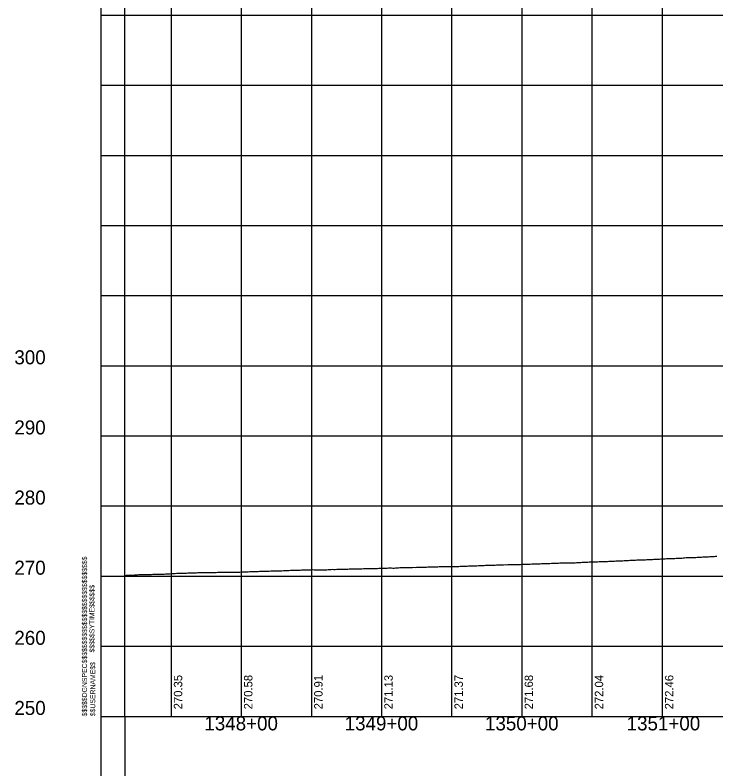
# Model space of a CAD drawing. Extents: x -90830 to 2015517, y -20856 to 836331.
# Drawn here: x 19162 to 19662, y 20025 to 20563 of the extents above; entities that cross this region are included whole.
import ezdxf

# ---------------------------------------------------------------- set-up
doc = ezdxf.new("R2010")
doc.units = 0
for name, color, linetype in [('Level 1', 7, 'Continuous'), ('RD_DDB_ElevTX', 7, 'Continuous'), ('RD_DDB_Profile_EX', 7, 'Continuous'), ('RD_DDB_StaTX', 7, 'Continuous'), ('RD_DDB_StripGrade', 7, 'Continuous'), ('RD_GPK_Profile_Cell', 7, 'Continuous'), ('RD_SHT_MatchLine', 7, 'Continuous')]:
    doc.layers.add(name, color=color, linetype=linetype)

msp = doc.modelspace()

# ---------------------------------------------------------------- linework, layer by layer
at = {"layer": 'Level 1'}
for p, q in [((19223.46, 21062.87), (19223.46, 20562.87)), ((19273.46, 21062.87), (19273.46, 20562.87)), ((19323.46, 21062.87), (19323.46, 20562.87)), ((19373.46, 21062.87), (19373.46, 20562.87)), ((19423.46, 21062.87), (19423.46, 20562.87)), ((19473.46, 21062.87), (19473.46, 20562.87)), ((19523.46, 21062.87), (19523.46, 20562.87)), ((19573.46, 21062.87), (19573.46, 20562.87)), ((19623.46, 21062.87), (19623.46, 20562.87)), ((19223.46, 20562.87), (20823.46, 20562.87)), ((19223.46, 20562.87), (20823.46, 20562.87)), ((19223.46, 20562.87), (19223.46, 20062.87)), ((19273.46, 20562.87), (19273.46, 20062.87)), ((19323.46, 20562.87), (19323.46, 20062.87)), ((19373.46, 20562.87), (19373.46, 20062.87)), ((19423.46, 20562.87), (19423.46, 20062.87)), ((19473.46, 20562.87), (19473.46, 20062.87)), ((19523.46, 20562.87), (19523.46, 20062.87)), ((19573.46, 20562.87), (19573.46, 20062.87)), ((19623.46, 20562.87), (19623.46, 20062.87)), ((19223.46, 20512.87), (20823.46, 20512.87)), ((19223.46, 20462.87), (20823.46, 20462.87)), ((19223.46, 20412.87), (20823.46, 20412.87)), ((19223.46, 20362.87), (20823.46, 20362.87)), ((19223.46, 20312.87), (20823.46, 20312.87)), ((19223.46, 20262.87), (20823.46, 20262.87)), ((19223.46, 20212.87), (20823.46, 20212.87)), ((19223.46, 20162.87), (20823.46, 20162.87)), ((19223.46, 20112.87), (20823.46, 20112.87)), ((19223.46, 20062.87), (20823.46, 20062.87))]:
    msp.add_line(p, q, dxfattribs=at)
at = {"layer": 'RD_DDB_Profile_EX'}
for points in [[(19640.51, 20176.02), (19641.51, 20176.02), (19642.51, 20176.04), (19643.51, 20176.13), (19644.51, 20176.17), (19645.51, 20176.18), (19646.51, 20176.22), (19647.51, 20176.24), (19648.51, 20176.33), (19649.51, 20176.33), (19650.51, 20176.38), (19651.51, 20176.48), (19652.51, 20176.52), (19653.51, 20176.53), (19654.51, 20176.62), (19655.51, 20176.67), (19656.51, 20176.72), (19657.51, 20176.77), (19658.51, 20176.83), (19659.51, 20176.92), (19660.51, 20176.93), (19661.51, 20176.98), (19662.51, 20177.04)], [(19440.51, 20168.96), (19441.51, 20168.96), (19442.51, 20169.01), (19443.51, 20169.1), (19444.51, 20169.06), (19445.51, 20169.11), (19446.51, 20169.16), (19447.51, 20169.12), (19448.51, 20169.16), (19449.51, 20169.21), (19450.51, 20169.26), (19451.51, 20169.27), (19452.51, 20169.27), (19453.51, 20169.31), (19454.51, 20169.32), (19455.51, 20169.27), (19456.51, 20169.4), (19457.51, 20169.41), (19458.51, 20169.46), (19459.51, 20169.51), (19460.51, 20169.55), (19461.51, 20169.56), (19462.51, 20169.6), (19463.51, 20169.6), (19464.51, 20169.65), (19465.51, 20169.65), (19466.51, 20169.65), (19467.51, 20169.7), (19468.51, 20169.71), (19469.51, 20169.71), (19470.51, 20169.67), (19471.51, 20169.67), (19472.51, 20169.72), (19473.51, 20169.73), (19474.51, 20169.73), (19475.51, 20169.78), (19476.51, 20169.78), (19477.51, 20169.78), (19478.51, 20169.83), (19479.51, 20169.84), (19480.51, 20169.84), (19481.51, 20169.93), (19482.51, 20169.99), (19483.51, 20169.99), (19484.51, 20170.04), (19485.51, 20170.09), (19486.51, 20170.14), (19487.51, 20170.18), (19488.51, 20170.23), (19489.51, 20170.28), (19490.51, 20170.24), (19491.51, 20170.28), (19492.51, 20170.37), (19493.51, 20170.42), (19494.51, 20170.47), (19495.51, 20170.47), (19496.51, 20170.52), (19497.51, 20170.56), (19498.51, 20170.61), (19499.51, 20170.62), (19500.51, 20170.68), (19501.51, 20170.73), (19502.51, 20170.78), (19503.51, 20170.78), (19504.51, 20170.78), (19505.51, 20170.79), (19506.51, 20170.9), (19507.51, 20170.99), (19508.51, 20170.98), (19509.51, 20170.95), (19510.51, 20170.99), (19511.51, 20171.03), (19512.51, 20171), (19513.51, 20171.04), (19514.51, 20171.04), (19515.51, 20171.04), (19516.51, 20171.04), (19517.51, 20171.05), (19518.51, 20171.09), (19519.51, 20171.09), (19520.51, 20171.1), (19521.51, 20171.19), (19522.51, 20171.24), (19523.51, 20171.29), (19524.51, 20171.33), (19525.51, 20171.33), (19526.51, 20171.39), (19527.51, 20171.43), (19528.51, 20171.44), (19529.51, 20171.49), (19530.51, 20171.53), (19531.51, 20171.55), (19532.51, 20171.64), (19533.51, 20171.68), (19534.51, 20171.64), (19535.51, 20171.69), (19536.51, 20171.73), (19537.51, 20171.74), (19538.51, 20171.79), (19539.51, 20171.84), (19540.51, 20171.88)], [(19540.51, 20171.88), (19541.51, 20171.88), (19542.51, 20171.93), (19543.51, 20171.93), (19544.51, 20171.98), (19545.51, 20172.02), (19546.51, 20172.02), (19547.51, 20172.02), (19548.51, 20172.07), (19549.51, 20172.13), (19550.51, 20172.22), (19551.51, 20172.22), (19552.51, 20172.24), (19553.51, 20172.29), (19554.51, 20172.33), (19555.51, 20172.29), (19556.51, 20172.3), (19557.51, 20172.34), (19558.51, 20172.34), (19559.51, 20172.35), (19560.51, 20172.4), (19561.51, 20172.45), (19562.51, 20172.5), (19563.51, 20172.56), (19564.51, 20172.61), (19565.51, 20172.66), (19566.51, 20172.71), (19567.51, 20172.75), (19568.51, 20172.75), (19569.51, 20172.76), (19570.51, 20172.86), (19571.51, 20172.95), (19572.51, 20173), (19573.51, 20173.05), (19574.51, 20173.09), (19575.51, 20173.09), (19576.51, 20173.1), (19577.51, 20173.15), (19578.51, 20173.19), (19579.51, 20173.19), (19580.51, 20173.24), (19581.51, 20173.29), (19582.51, 20173.3), (19583.51, 20173.34), (19584.51, 20173.39), (19585.51, 20173.45), (19586.51, 20173.49), (19587.51, 20173.49), (19588.51, 20173.55), (19589.51, 20173.64), (19590.51, 20173.65), (19591.51, 20173.74), (19592.51, 20173.78), (19593.51, 20173.78), (19594.51, 20173.78), (19595.51, 20173.84), (19596.51, 20173.92), (19597.51, 20173.93), (19598.51, 20173.98), (19599.51, 20174.07), (19600.51, 20174.15), (19601.51, 20174.12), (19602.51, 20174.2), (19603.51, 20174.21), (19604.51, 20174.27), (19605.51, 20174.36), (19606.51, 20174.37), (19607.51, 20174.42), (19608.51, 20174.46), (19609.51, 20174.45), (19610.51, 20174.37), (19611.51, 20174.4), (19612.51, 20174.63), (19613.51, 20174.68), (19614.51, 20174.73), (19615.51, 20174.77), (19616.51, 20174.77), (19617.51, 20174.83), (19618.51, 20174.87), (19619.51, 20174.92), (19620.51, 20174.97), (19621.51, 20175.03), (19622.51, 20175.12), (19623.51, 20175.16), (19624.51, 20175.17), (19625.51, 20175.22), (19626.51, 20175.31), (19627.51, 20175.31), (19628.51, 20175.36), (19629.51, 20175.41), (19630.51, 20175.46), (19631.51, 20175.46), (19632.51, 20175.52), (19633.51, 20175.62), (19634.51, 20175.66), (19635.51, 20175.67), (19636.51, 20175.72), (19637.51, 20175.78), (19638.51, 20175.83), (19639.51, 20175.93), (19640.51, 20176.02)], [(19240.51, 20163.33), (19241.51, 20163.43), (19242.51, 20163.43), (19243.51, 20163.54), (19244.51, 20163.67), (19245.51, 20163.58), (19246.51, 20163.65), (19247.51, 20163.77), (19248.51, 20163.78), (19249.51, 20163.85), (19250.51, 20163.92), (19251.51, 20163.92), (19252.51, 20163.94), (19253.51, 20163.96), (19254.51, 20163.96), (19255.51, 20163.99), (19256.51, 20163.98), (19257.51, 20163.93), (19258.51, 20163.95), (19259.51, 20164.11), (19260.51, 20164.16), (19261.51, 20164.2), (19262.51, 20164.21), (19263.51, 20164.17), (19264.51, 20164.21), (19265.51, 20164.31), (19266.51, 20164.32), (19267.51, 20164.32), (19268.51, 20164.32), (19269.51, 20164.38), (19270.51, 20164.39), (19271.51, 20164.48), (19272.51, 20164.53), (19273.51, 20164.62), (19274.51, 20164.71), (19275.51, 20164.75), (19276.51, 20164.83), (19277.51, 20164.87), (19278.51, 20164.92), (19279.51, 20164.93), (19280.51, 20164.97), (19281.51, 20165.02), (19282.51, 20165.07), (19283.51, 20165.07), (19284.51, 20165.07), (19285.51, 20165.15), (19286.51, 20165.2), (19287.51, 20165.16), (19288.51, 20165.16), (19289.51, 20165.21), (19290.51, 20165.21), (19291.51, 20165.29), (19292.51, 20165.38), (19293.51, 20165.43), (19294.51, 20165.43), (19295.51, 20165.43), (19296.51, 20165.47), (19297.51, 20165.52), (19298.51, 20165.52), (19299.51, 20165.52), (19300.51, 20165.53), (19301.51, 20165.49), (19302.51, 20165.53), (19303.51, 20165.53), (19304.51, 20165.53), (19305.51, 20165.53), (19306.51, 20165.58), (19307.51, 20165.58), (19308.51, 20165.58), (19309.51, 20165.58), (19310.51, 20165.58), (19311.51, 20165.58), (19312.51, 20165.58), (19313.51, 20165.62), (19314.51, 20165.67), (19315.51, 20165.67), (19316.51, 20165.71), (19317.51, 20165.67), (19318.51, 20165.66), (19319.51, 20165.71), (19320.51, 20165.71), (19321.51, 20165.75), (19322.51, 20165.75), (19323.51, 20165.8), (19324.51, 20165.89), (19325.51, 20165.95), (19326.51, 20165.99), (19327.51, 20165.95), (19328.51, 20165.99), (19329.51, 20166.09), (19330.51, 20166.1), (19331.51, 20166.1), (19332.51, 20166.09), (19333.51, 20166.18), (19334.51, 20166.23), (19335.51, 20166.24), (19336.51, 20166.28), (19337.51, 20166.33), (19338.51, 20166.33), (19339.51, 20166.32), (19340.51, 20166.37)], [(19340.51, 20166.37), (19341.51, 20166.41), (19342.51, 20166.46), (19343.51, 20166.51), (19344.51, 20166.6), (19345.51, 20166.69), (19346.51, 20166.7), (19347.51, 20166.69), (19348.51, 20166.69), (19349.51, 20166.69), (19350.51, 20166.73), (19351.51, 20166.74), (19352.51, 20166.69), (19353.51, 20166.78), (19354.51, 20166.83), (19355.51, 20166.92), (19356.51, 20166.93), (19357.51, 20166.97), (19358.51, 20167.02), (19359.51, 20167.07), (19360.51, 20167.07), (19361.51, 20167.12), (19362.51, 20167.12), (19363.51, 20167.16), (19364.51, 20167.21), (19365.51, 20167.21), (19366.51, 20167.25), (19367.51, 20167.26), (19368.51, 20167.25), (19369.51, 20167.29), (19370.51, 20167.34), (19371.51, 20167.38), (19372.51, 20167.38), (19373.51, 20167.43), (19374.51, 20167.48), (19375.51, 20167.4), (19376.51, 20167.39), (19377.51, 20167.4), (19378.51, 20167.4), (19379.51, 20167.4), (19380.51, 20167.4), (19381.51, 20167.4), (19382.51, 20167.45), (19383.51, 20167.46), (19384.51, 20167.46), (19385.51, 20167.51), (19386.51, 20167.56), (19387.51, 20167.61), (19388.51, 20167.7), (19389.51, 20167.67), (19390.51, 20167.66), (19391.51, 20167.71), (19392.51, 20167.71), (19393.51, 20167.76), (19394.51, 20167.81), (19395.51, 20167.85), (19396.51, 20167.86), (19397.51, 20167.86), (19398.51, 20167.86), (19399.51, 20167.86), (19400.51, 20167.95), (19401.51, 20168), (19402.51, 20168), (19403.51, 20168.01), (19404.51, 20168.01), (19405.51, 20168.06), (19406.51, 20168.11), (19407.51, 20168.12), (19408.51, 20168.17), (19409.51, 20168.17), (19410.51, 20168.18), (19411.51, 20168.22), (19412.51, 20168.18), (19413.51, 20168.23), (19414.51, 20168.28), (19415.51, 20168.28), (19416.51, 20168.29), (19417.51, 20168.33), (19418.51, 20168.38), (19419.51, 20168.39), (19420.51, 20168.39), (19421.51, 20168.48), (19422.51, 20168.49), (19423.51, 20168.53), (19424.51, 20168.58), (19425.51, 20168.59), (19426.51, 20168.59), (19427.51, 20168.63), (19428.51, 20168.68), (19429.51, 20168.68), (19430.51, 20168.68), (19431.51, 20168.63), (19432.51, 20168.63), (19433.51, 20168.68), (19434.51, 20168.78), (19435.51, 20168.84), (19436.51, 20168.89), (19437.51, 20168.9), (19438.51, 20168.95), (19439.51, 20168.95), (19440.51, 20168.96)]]:
    msp.add_lwpolyline(points, dxfattribs=at)
at = {"layer": 'RD_GPK_Profile_Cell'}
for q in [(19240.51, 21312.87), (21740.51, 20062.87), (19240.51, 18812.87)]:
    msp.add_line((19240.51, 20062.87), q, dxfattribs=at)
at = {"layer": 'RD_SHT_MatchLine'}
for p, q in [((19223.46, 20062.87), (19223.46, 19424)), ((19240.51, 20062.87), (19240.51, 19424))]:
    msp.add_line(p, q, dxfattribs=at)

# ---------------------------------------------------------------- texts
at = {"layer": 'Level 1'}
for s, p in [('$$$$$DGNSPEC$$$$$$$$$$$$$$$$$$$$$$$$$$$$', (19213.56, 20062.82)), ('$$$$$SYTIME$$$$$$', (19218.86, 20108.42)), ('$$USERNAME$$', (19219.46, 20062.97))]:
    msp.add_text(s, height=3.5436, rotation=90, dxfattribs=at).set_placement(p)
at = {"layer": 'RD_DDB_ElevTX'}
for s, p in [('300', (19161.8, 20313.87)), ('290', (19161.8, 20263.87)), ('280', (19161.8, 20213.87)), ('270', (19161.8, 20163.87)), ('260', (19161.8, 20113.87)), ('250', (19161.8, 20063.87))]:
    msp.add_text(s, height=10, dxfattribs=at).set_placement(p)
at = {"layer": 'RD_DDB_StaTX'}
for s, p in [('1348+00', (19297.21, 20052.87)), ('1349+00', (19397.21, 20052.87)), ('1350+00', (19497.21, 20052.87)), ('1351+00', (19598.17, 20052.87))]:
    msp.add_text(s, height=10, dxfattribs=at).set_placement(p)
at = {"layer": 'RD_DDB_StripGrade'}
for s, p in [('270.35', (19281.46, 20067.87)), ('270.58', (19331.46, 20067.87)), ('270.91', (19381.46, 20067.87)), ('271.13', (19431.46, 20067.87)), ('271.37', (19481.46, 20067.87)), ('271.68', (19531.46, 20067.87)), ('272.04', (19581.46, 20067.87)), ('272.46', (19631.46, 20067.87))]:
    msp.add_text(s, height=6, rotation=90, dxfattribs=at).set_placement(p)

doc.saveas('drawing.dxf')
